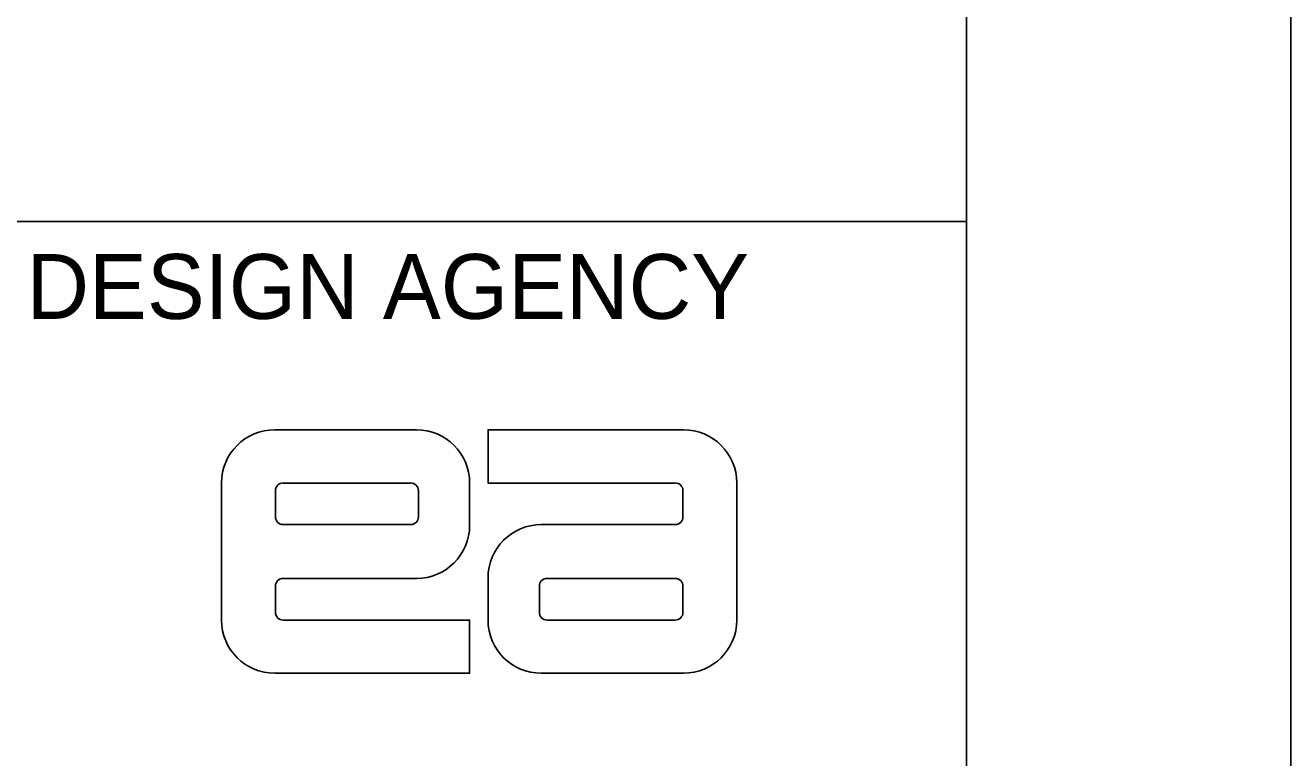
# Model space of a CAD drawing. Extents: x 0 to 34, y 0 to 22.
# Drawn here: x 32.048 to 34, y 3.673 to 4.803 of the extents above; entities that cross this region are included whole.
import ezdxf

# ---------------------------------------------------------------- set-up
doc = ezdxf.new("R2010")
doc.units = 0
for name, color, linetype in [('SH_Border', 7, 'Continuous'), ('SH_Cut_Line', 7, 'Continuous'), ('SH_Data', 7, 'Continuous'), ('SH_Text', 7, 'Continuous')]:
    doc.layers.add(name, color=color, linetype=linetype)

msp = doc.modelspace()

# ---------------------------------------------------------------- linework, layer by layer
at = {"layer": 'SH_Border'}
msp.add_line((32, 4.5), (33.5, 4.5), dxfattribs=at)
msp.add_lwpolyline([(1.5, 21.5), (33.5, 21.5), (33.5, 0.5), (1.5, 0.5)], close=True, dxfattribs=at)
at = {"layer": 'SH_Cut_Line'}
msp.add_lwpolyline([(0, 0), (34, 0), (34, 22), (0, 22)], close=True, dxfattribs=at)
at = {"layer": 'SH_Text'}
for p, q in [((32.6515, 4.1788), (32.433, 4.1788)), ((32.433, 4.1788), (32.6515, 4.1788)), ((32.762, 4.1788), (33.0635, 4.1788)), ((32.762, 4.0967), (32.762, 4.1788)), ((32.351, 4.0967), (32.351, 3.8852)), ((32.351, 3.8852), (32.351, 4.0967)), ((32.434, 4.0444), (32.434, 4.0849)), ((32.434, 4.0849), (32.434, 4.0444)), ((32.4459, 4.0967), (32.6426, 4.0967)), ((32.6426, 4.0967), (32.4459, 4.0967)), ((32.6545, 4.0849), (32.6545, 4.0444)), ((32.6545, 4.0444), (32.6545, 4.0849)), ((32.7336, 4.0315), (32.7336, 4.0967)), ((32.7336, 4.0967), (32.7336, 4.0315)), ((33.0507, 4.0967), (32.762, 4.0967)), ((33.0626, 4.0849), (33.0626, 4.0444)), ((33.0626, 4.0444), (33.0626, 4.0849)), ((33.1456, 3.8852), (33.1456, 4.0967)), ((33.1456, 4.0967), (33.1456, 3.8852)), ((32.6426, 4.0325), (32.4459, 4.0325)), ((32.4459, 4.0325), (32.6426, 4.0325)), ((33.0507, 4.0325), (32.8441, 4.0325)), ((32.8441, 4.0325), (33.0507, 4.0325)), ((32.4459, 3.9494), (32.6515, 3.9494)), ((32.6515, 3.9494), (32.4459, 3.9494)), ((32.762, 3.9504), (32.762, 3.8852)), ((32.762, 3.8852), (32.762, 3.9504)), ((32.853, 3.9494), (33.0507, 3.9494)), ((33.0507, 3.9494), (32.853, 3.9494)), ((32.434, 3.8971), (32.434, 3.9376)), ((32.434, 3.9376), (32.434, 3.8971)), ((32.8411, 3.8971), (32.8411, 3.9376)), ((32.8411, 3.9376), (32.8411, 3.8971)), ((33.0626, 3.9376), (33.0626, 3.8971)), ((33.0626, 3.8971), (33.0626, 3.9376)), ((32.4459, 3.8852), (32.7336, 3.8852)), ((32.7336, 3.8852), (32.7336, 3.8031)), ((33.0507, 3.8852), (32.853, 3.8852)), ((32.853, 3.8852), (33.0507, 3.8852)), ((32.7336, 3.8031), (32.433, 3.8031)), ((32.8441, 3.8031), (33.0635, 3.8031)), ((33.0635, 3.8031), (32.8441, 3.8031))]:
    msp.add_line(p, q, dxfattribs=at)
for points in [[(33.0635, 4.1788), (32.762, 4.1788), (32.762, 4.0967), (33.0507, 4.0967)], [(32.433, 3.8031), (32.7336, 3.8031), (32.7336, 3.8852), (32.4459, 3.8852)]]:
    msp.add_lwpolyline(points, dxfattribs=at)
for centre, radius, start, end in [((32.433, 4.0967), 0.0821, 90, 180), ((32.433, 4.0967), 0.0821, 90, 180), ((32.6515, 4.0967), 0.0821, 0, 90), ((32.6515, 4.0967), 0.0821, 0, 90), ((33.0635, 4.0967), 0.0821, 0, 90), ((33.0635, 4.0967), 0.0821, 0, 90), ((32.4459, 4.0849), 0.0119, 90, 180), ((32.4459, 4.0849), 0.0119, 90, 180), ((32.6426, 4.0849), 0.0119, 0, 90), ((32.6426, 4.0849), 0.0119, 0, 90), ((33.0507, 4.0849), 0.0119, 0, 90), ((33.0507, 4.0849), 0.0119, 0, 90), ((32.4459, 4.0444), 0.0119, 180, 270), ((32.4459, 4.0444), 0.0119, 180, 270), ((32.6426, 4.0444), 0.0119, 270, 0), ((32.6426, 4.0444), 0.0119, 270, 0), ((33.0507, 4.0444), 0.0119, 270, 0), ((33.0507, 4.0444), 0.0119, 270, 0), ((32.6515, 4.0315), 0.0821, 270, 360), ((32.6515, 4.0315), 0.0821, 270, 360), ((32.8441, 3.9504), 0.0821, 90, 180), ((32.8441, 3.9504), 0.0821, 90, 180), ((32.4459, 3.9376), 0.0119, 90, 180), ((32.4459, 3.9376), 0.0119, 90, 180), ((32.853, 3.9376), 0.0119, 90, 180), ((32.853, 3.9376), 0.0119, 90, 180), ((33.0507, 3.9376), 0.0119, 0, 90), ((33.0507, 3.9376), 0.0119, 0, 90), ((32.433, 3.8852), 0.0821, 180, 270), ((32.433, 3.8852), 0.0821, 180, 270), ((32.4459, 3.8971), 0.0119, 180, 270), ((32.4459, 3.8971), 0.0119, 180, 270), ((32.8441, 3.8852), 0.0821, 180, 270), ((32.8441, 3.8852), 0.0821, 180, 270), ((32.853, 3.8971), 0.0119, 180, 270), ((32.853, 3.8971), 0.0119, 180, 270), ((33.0507, 3.8971), 0.0119, 270, 0), ((33.0507, 3.8971), 0.0119, 270, 0), ((33.0635, 3.8852), 0.0821, 270, 360), ((33.0635, 3.8852), 0.0821, 270, 360)]:
    msp.add_arc(centre, radius, start, end, dxfattribs=at)

# ---------------------------------------------------------------- texts
at = {"layer": 'SH_Data'}
msp.add_text('DESIGN AGENCY', height=0.1, dxfattribs=at).set_placement((32.05, 4.35))

doc.saveas('drawing.dxf')
